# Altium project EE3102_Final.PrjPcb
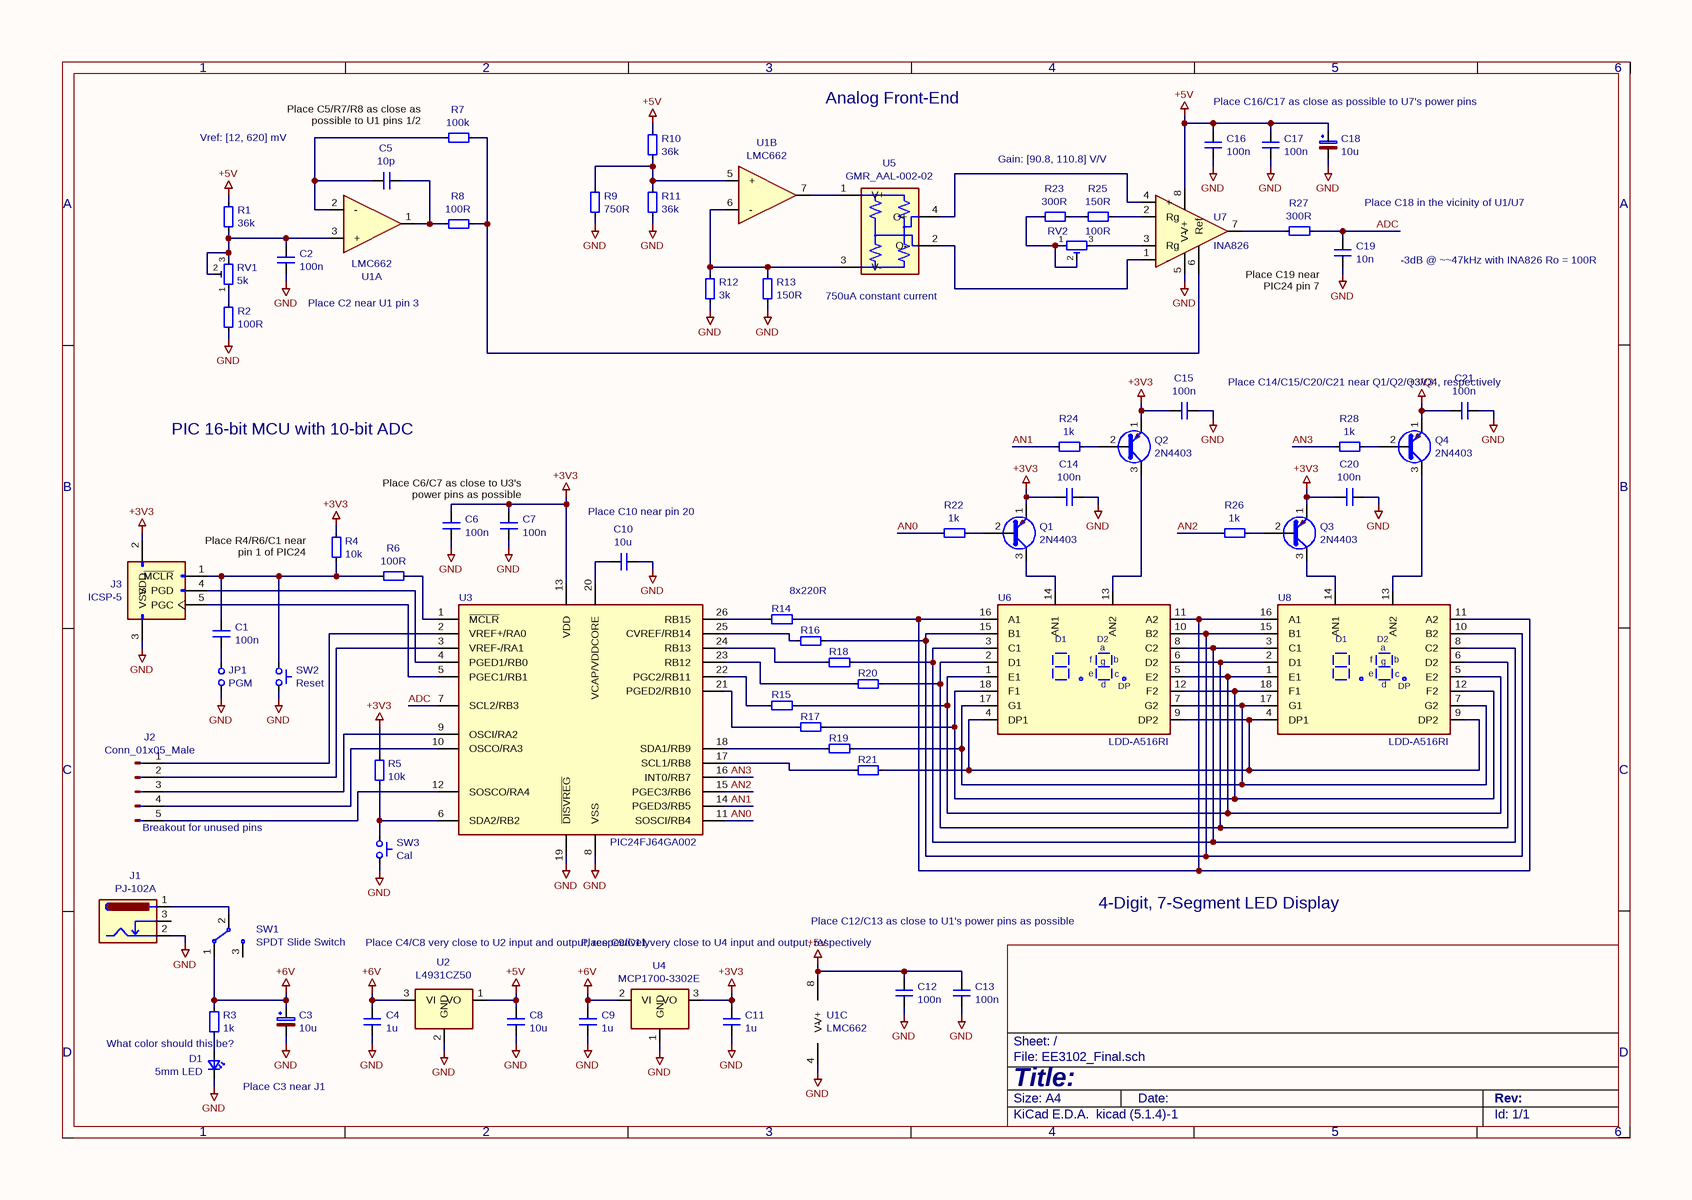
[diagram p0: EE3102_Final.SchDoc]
1 sheet, 71 parts. Net scope: global (net labels, ports and power ports of the same name join across sheets).

## Sheet EE3102_Final.SchDoc
size 297 x 210 mm

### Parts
C1  100n
C2  100n
C3  10u
C4  1u
C5  10p
C6  100n
C7  100n
C8  10u
C9  1u
C10  10u
C11  1u
C12  100n
C13  100n
C14  100n
C15  100n
C16  100n
C17  100n
C18  10u
C19  10n
C20  100n
C21  100n
D1  5mm LED
J1  PJ-102A
J2  Conn_01x05_Male
J3  ICSP-5
JP1  PGM
Q1  2N4403
Q2  2N4403
Q3  2N4403
Q4  2N4403
R1  36k
R2  100R
R3  1k
R4  10k
R5  10k
R6  100R
R7  100k
R8  100R
R9  750R
R10  36k
R11  36k
R12  3k
R13  150R
R14  220R  (value not drawn)
R15  220R  (value not drawn)
R16  220R  (value not drawn)
R17  220R  (value not drawn)
R18  220R  (value not drawn)
R19  220R  (value not drawn)
R20  220R  (value not drawn)
R21  220R  (value not drawn)
R22  1k
R23  300R
R24  1k
R25  150R
R26  1k
R27  300R
R28  1k
RV1  5k
RV2  100R
SW1  SPDT Slide Switch
SW2  Reset
SW3  Cal
U1  LMC662  (parts A,B,C of 3)
U2  L4931CZ50
U3  PIC24FJ64GA002
U4  MCP1700-3302E
U5  GMR_AAL-002-02
U6  LDD-A516RI  [DA56-11CGKWA]
U7  INA826
U8  LDD-A516RI  [DA56-11CGKWA]

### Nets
+3V3: C6.1 C7.1 C11.1 C14.2 C15.2 C20.2 C21.2 J3.2(VDD) Q1.1(E) Q2.1(E) Q3.1(E) Q4.1(E) R4.2 R5.2 U3.13(VDD) U4.3(VO)
+5V: C8.1 C12.1 C13.1 C16.1 C17.1 C18.1 R1.2 R10.1 U1.8(V+) U2.1(VO) U7.8(V+)
+6V: C3.1 C4.1 C9.1 R3.2 SW1.1(A) U2.3(VI) U4.2(VI)
GND: C2.2 C3.2 C4.2 C6.2 C7.2 C8.2 C9.2 C10.1 C11.2 C12.2 C13.2 C14.1 C15.1 C16.2 C17.2 C18.2 C19.1 C20.1 C21.1 D1.1(K) J1.2 J3.3(VSS) JP1.2 R2.1 R9.2 R11.2 R12.2 R13.2 SW2.2 SW3.2 U1.4(V-) U2.2(GND) U3.8(VSS) U3.19(~{DISVREG}) U4.1(GND) U7.5(V-)
ADC: C19.2 R27.1 U3.7(SCL2/RB3)
AN0: R22.2 U3.11(SOSCI/RB4)
AN1: R24.2 U3.14(PGED3/RB5)
AN2: R26.2 U3.15(PGEC3/RB6)
AN3: R28.2 U3.16(INT0/RB7)
NetC1_1: C1.1 J3.1(~{MCLR}) R4.1 R6.2 SW2.1
NetC1_2: C1.2 JP1.1
NetC2_1: C2.1 R1.1 RV1.2(W) RV1.3(CW) U1.3(+)
NetC5_1: C5.1 R7.2 U1.2(-)
NetC5_2: C5.2 R8.2 U1.1
NetC10_2: C10.2 U3.20(VCAP/VDDCORE)
NetD1_2: D1.2(A) R3.1
NetJ1_1: J1.1 SW1.2(B)
NetJ2_1: J2.1(Pin_1) U3.2(VREF+/RA0)
NetJ2_2: J2.2(Pin_2) U3.3(VREF-/RA1)
NetJ2_3: J2.3(Pin_3) U3.9(OSCI/RA2)
NetJ2_4: J2.4(Pin_4) U3.10(OSCO/RA3)
NetJ2_5: J2.5(Pin_5) U3.12(SOSCO/RA4)
NetJ3_4: J3.4(PGD) U3.4(PGED1/RB0)
NetJ3_5: J3.5(PGC) U3.5(PGEC1/RB1)
NetQ1_2: Q1.2(B) R22.1
NetQ1_3: Q1.3(C) U6.14(AN1)
NetQ2_2: Q2.2(B) R24.1
NetQ2_3: Q2.3(C) U6.13(AN2)
NetQ3_2: Q3.2(B) R26.1
NetQ3_3: Q3.3(C) U8.14(AN1)
NetQ4_2: Q4.2(B) R28.1
NetQ4_3: Q4.3(C) U8.13(AN2)
NetR2_2: R2.2 RV1.1(CCW)
NetR5_1: R5.1 SW3.1 U3.6(SDA2/RB2)
NetR6_1: R6.1 U3.1(~{MCLR})
NetR7_1: R7.1 R8.1 U7.6(Ref)
NetR9_1: R9.1 R10.2 R11.1 U1.5(+)
NetR12_1: R12.1 R13.1 U1.6(-) U5.3(V-)
NetR14_1: R14.1 U3.26(RB15)
NetR14_2: R14.2 U6.11(A2) U6.16(A1) U8.11(A2) U8.16(A1)
NetR15_1: R15.1 U3.22(PGC2/RB11)
NetR15_2: R15.2 U6.1(E1) U6.5(E2) U8.1(E1) U8.5(E2)
NetR16_1: R16.1 U3.25(CVREF/RB14)
NetR16_2: R16.2 U6.10(B2) U6.15(B1) U8.10(B2) U8.15(B1)
NetR17_1: R17.1 U3.21(PGED2/RB10)
NetR17_2: R17.2 U6.12(F2) U6.18(F1) U8.12(F2) U8.18(F1)
NetR18_1: R18.1 U3.24(RB13)
NetR18_2: R18.2 U6.3(C1) U6.8(C2) U8.3(C1) U8.8(C2)
NetR19_1: R19.1 U3.18(SDA1/RB9)
NetR19_2: R19.2 U6.7(G2) U6.17(G1) U8.7(G2) U8.17(G1)
NetR20_1: R20.1 U3.23(RB12)
NetR20_2: R20.2 U6.2(D1) U6.6(D2) U8.2(D1) U8.6(D2)
NetR21_1: R21.1 U3.17(SCL1/RB8)
NetR21_2: R21.2 U6.4(DP1) U6.9(DP2) U8.4(DP1) U8.9(DP2)
NetR23_1: R23.1 R25.2
NetR23_2: R23.2 RV2.1(CCW) RV2.2(W)
NetR25_1: R25.1 U7.2(Rg)
NetR27_2: R27.2 U7.7
NetRV2_3: RV2.3(CW) U7.3(Rg)
NetU1_7: U1.7 U5.1(V+)
NetU5_2: U5.2(O-) U7.1(-)
NetU5_4: U5.4(O+) U7.4(+)

Not connected (* = marked no-connect by the designer): J1 3; SW1 3(C); U3 27(VSS) 28(VDD)

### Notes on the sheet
- Vref: [12, 620] mV
- (near R7) Place C5/R7/R8 as close as
  possible to U1 pins 1/2
- Analog Front-End
- Place C16/C17 as close as
  possible to U7's power pins
- Gain: [90.8, 110.8] V/V
- Place C18 in the vicinity of U1/U7
- Place C19 near
  PIC24 pin 7
- -3dB @ ~47kHz with
  INA826 Ro = 100R
- Place C2 near U1 pin 3
- (near U5) 750uA constant current
- (near C21) Place C14/C15/C20/C21 near
  Q1/Q2/Q3/Q4, respectively
- PIC 16-bit MCU with 10-bit ADC
- (near C7) Place C6/C7 as close to U3's
  power pins as possible
- (near R4) Place R4/R6/C1 near
  pin 1 of PIC24
- (near C10) Place C10 near pin 20
- (near R14) 8x220R
- (near J2) Breakout for unused pins
- Place C12/C13 as close
  to U1's power pins as possible
- 4-Digit, 7-Segment LED Display
- Place C4/C8 very close to U2
  input and output, respectively
- Place C9/C11 very close to U4
  input and output, respectively
- What color
  should this be?
- (near D1) Place C3 near J1

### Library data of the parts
C1 C2 C4-C17 C19-C21 = C_Small
C3 C18 = CP_Small
D1 = LED_Small
J1 = Barrel_Jack_Switch
J3 = Microchip_PICkit_ICSP-5
JP1 = Jumper_NO_Small
R1-R28 = R_Small
RV1 RV2 = R_POT_TRIM_Small
SW1 = SW_SPDT_Small
SW2 SW3 = SW_Push_Small
U4 = MCP1700-3302E_TO92
U5 = GMR_AAL-002-02-user_Sensor
U7 = INA826-user_Amplifier_Instrumentation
